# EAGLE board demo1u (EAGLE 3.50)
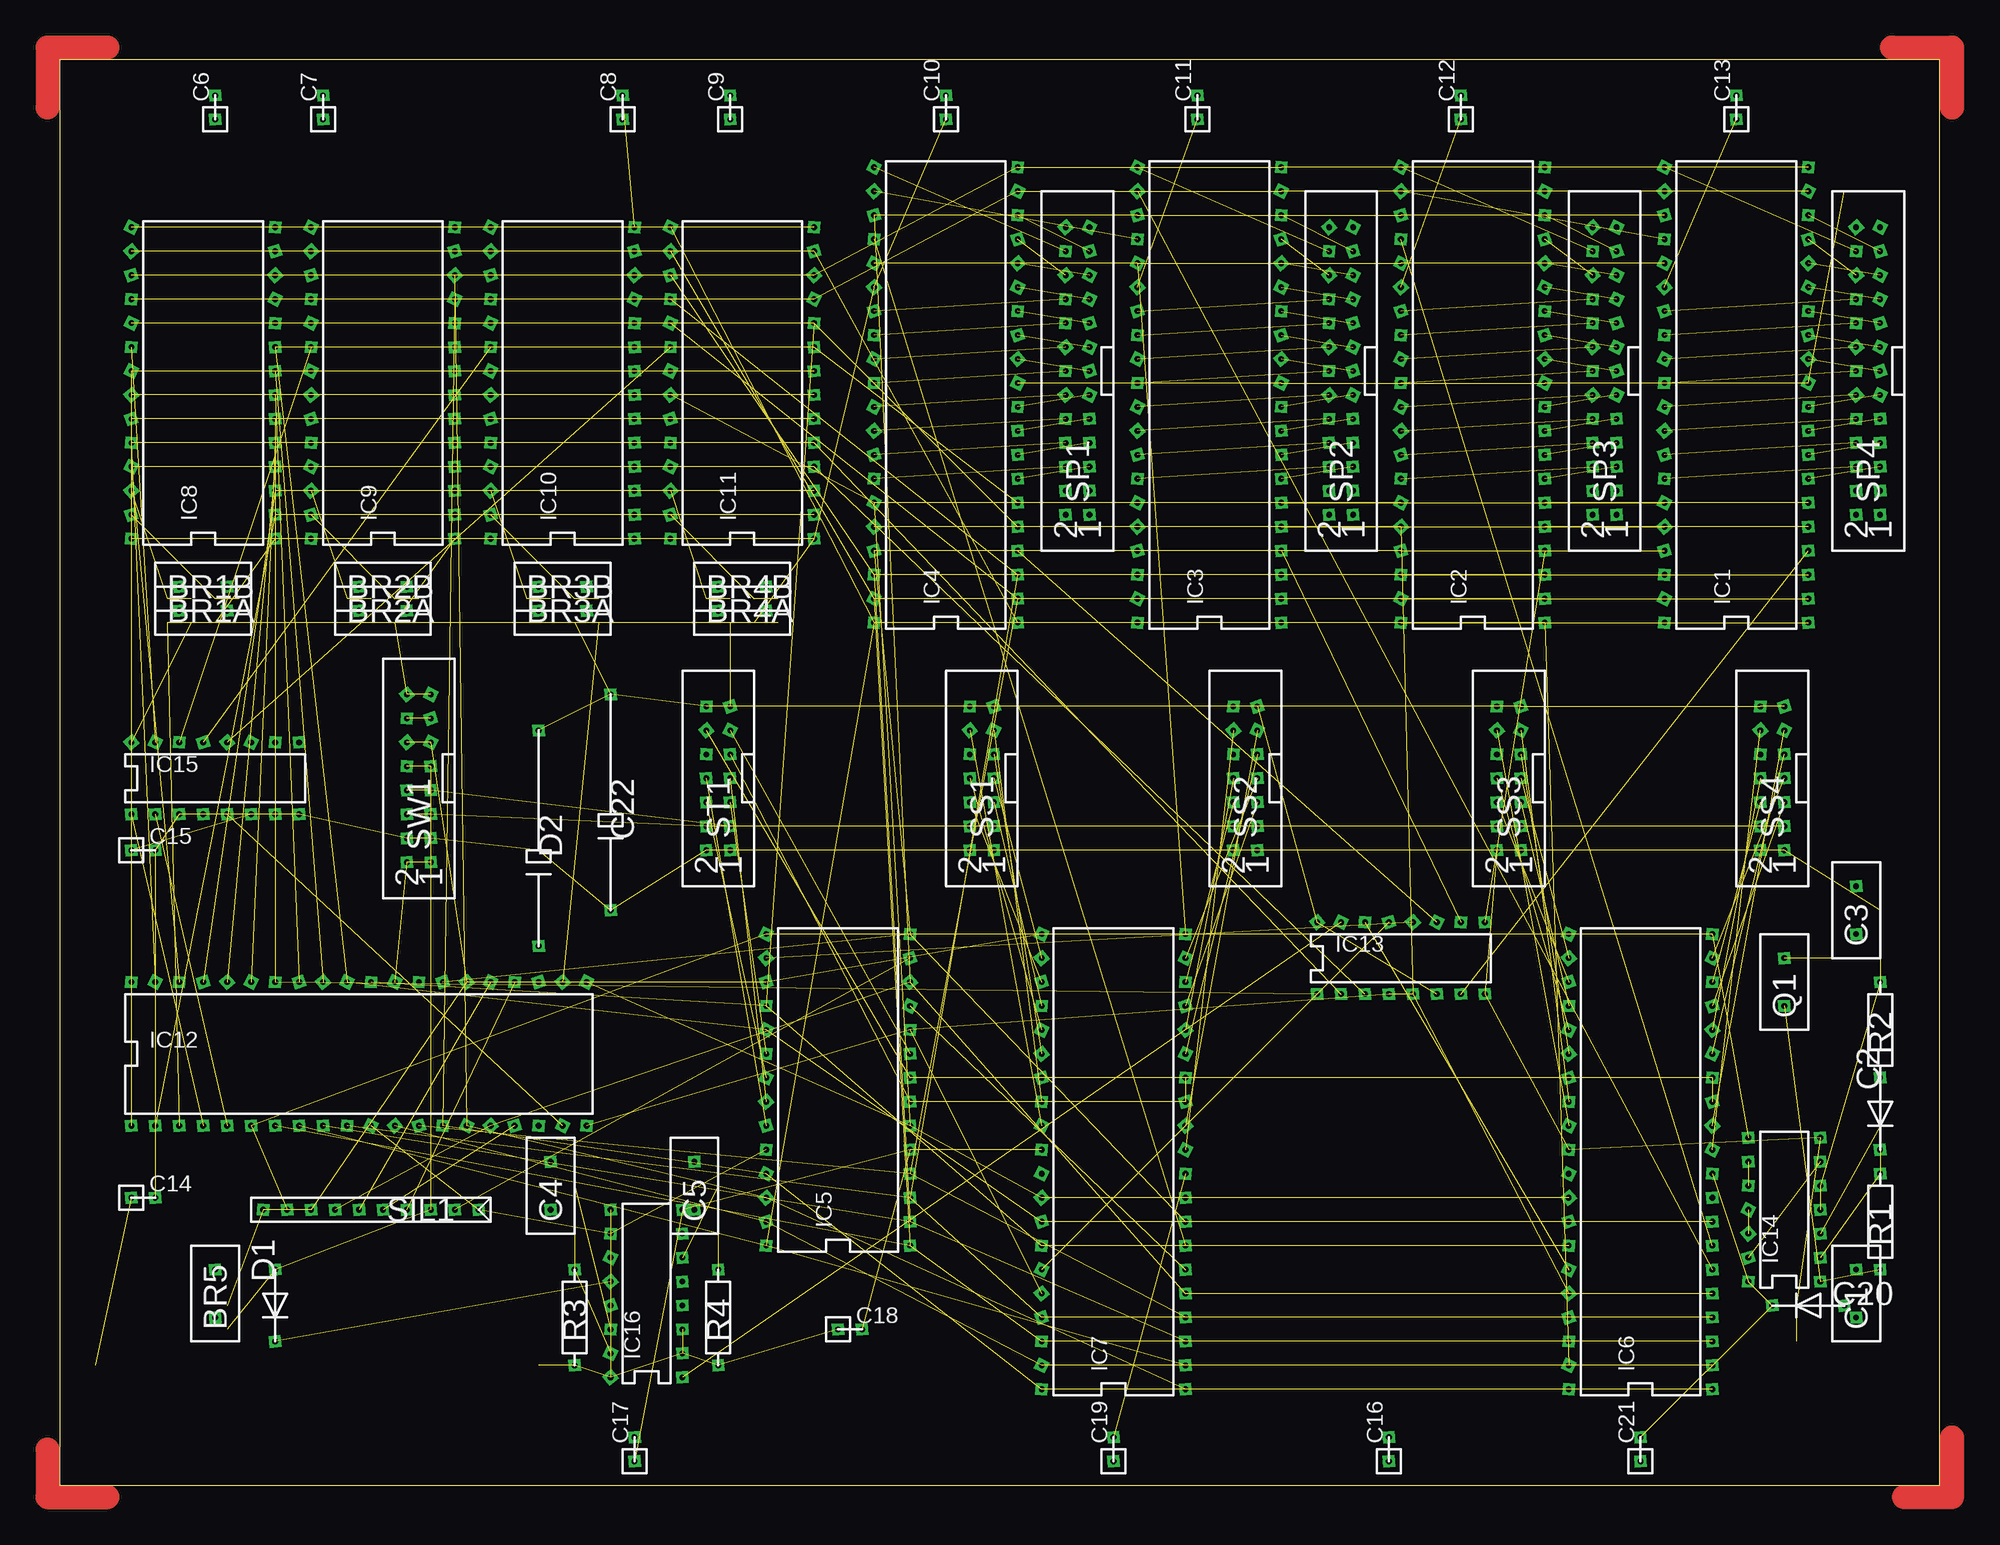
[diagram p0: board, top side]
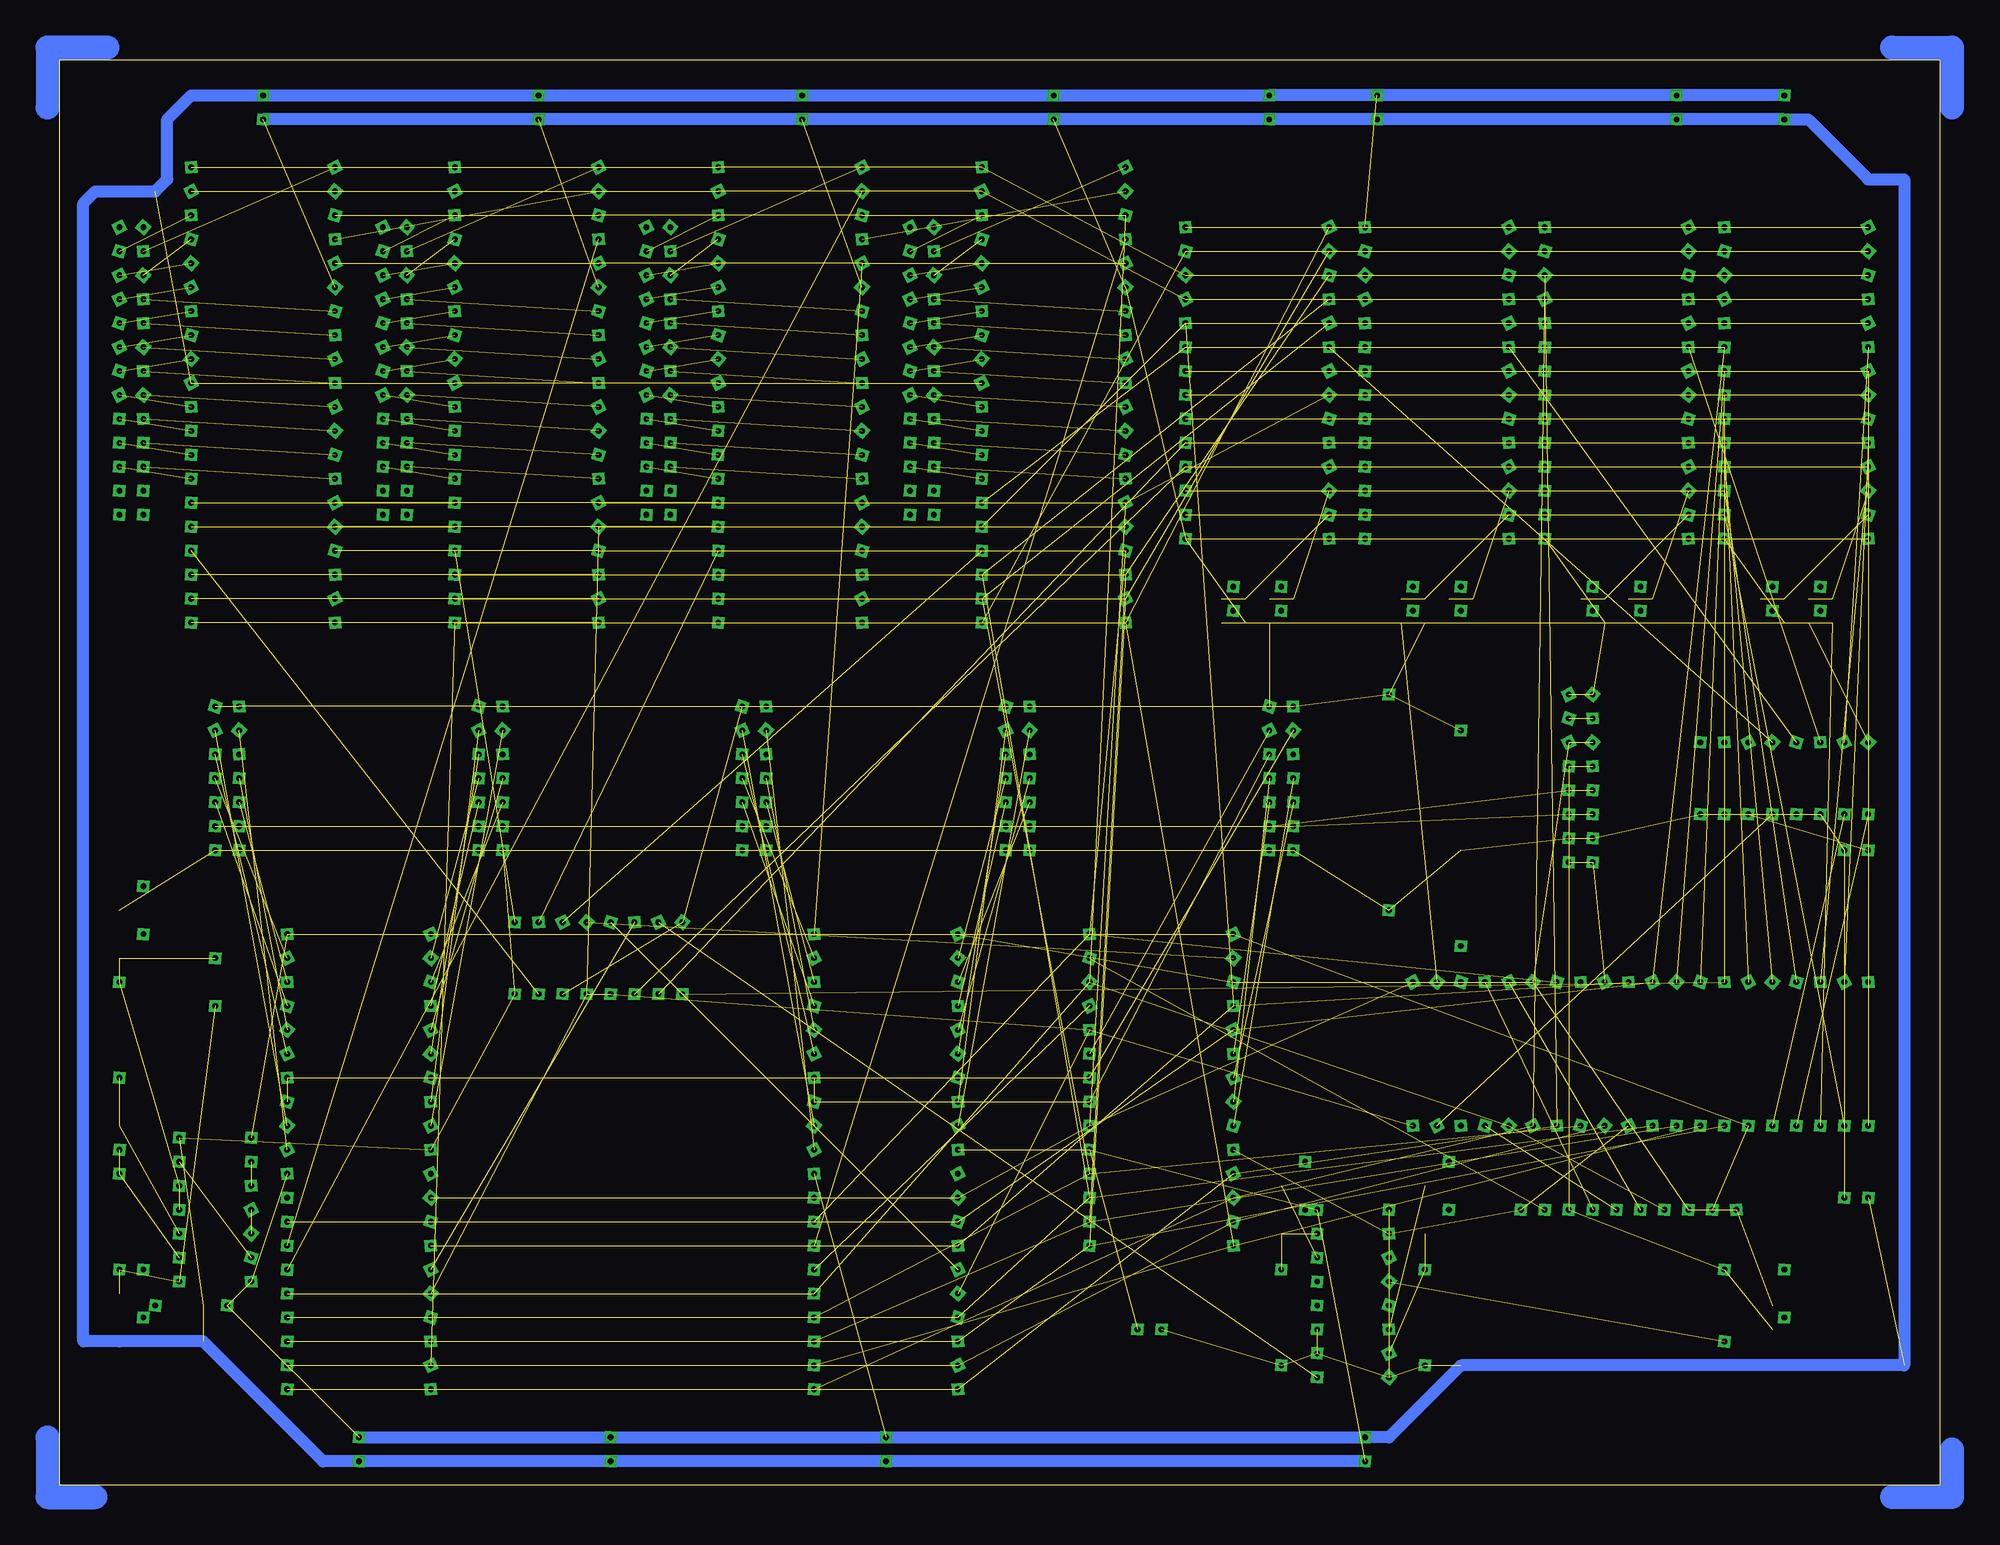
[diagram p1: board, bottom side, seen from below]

Size 199.36 x 151.16 mm. Coordinates in mm from the lower left corner, seen from the top.
Outline: 0,0.03 199.37,0 199.37,151.16 0,151.16 0,0.03
Copper layers used: Top, Bottom
tRestrict: area 5.1,5.1 to 7.6,7.6; area 2.5,2.6 to 10.2,10.2; area 5.1,142.3 to 7.6,144.8; area 2.5,139.7 to 10.2,147.3; area 191.8,5.1 to 194.3,7.6; area 189.2,2.6 to 196.9,10.2; area 191.8,142.3 to 194.3,144.8; area 189.2,139.7 to 196.9,147.3; area 34.3,6.4 to 36.8,8.9; area 47,6.4 to 49.5,8.9; area 34.3,141 to 36.8,143.5; area 47,141 to 49.5,143.5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
bRestrict: area 5.1,5.1 to 7.6,7.6; area 2.5,2.6 to 10.2,10.2; area 5.1,142.3 to 7.6,144.8; area 2.5,139.7 to 10.2,147.3; area 191.8,5.1 to 194.3,7.6; area 189.2,2.6 to 196.9,10.2; area 191.8,142.3 to 194.3,144.8; area 189.2,139.7 to 196.9,147.3; area 34.3,6.4 to 36.8,8.9; area 47,6.4 to 49.5,8.9; area 34.3,141 to 36.8,143.5; area 47,141 to 49.5,143.5

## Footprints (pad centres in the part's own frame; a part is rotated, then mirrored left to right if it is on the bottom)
 = drill 0.61 pad 1.27 square:  2.54,2.54;  7.62,2.54
.5 = drill 0.61 pad 1.27 square:  0,0;  7.62,0
.5' = drill 0.61 pad 1.27 square:  0,0;  2.54,0
2.5 = drill 0.61 pad 1.27 square:  0,0;  22.86,0
L40 = drill 0.61 pad 1.27 square:  0,0;  2.54,0;  5.08,0;  7.62,0;  10.16,0;  12.7,0;  15.24,0;  17.78,0;  20.32,0;  22.86,0;  25.4,0;  27.94,0;  30.48,0;  33.02,0;  35.56,0;  38.1,0;  40.64,0;  43.18,0;  45.72,0;  48.26,0;  48.26,15.24;  45.72,15.24;  43.18,15.24;  40.64,15.24;  38.1,15.24;  35.56,15.24;  33.02,15.24;  30.48,15.24;  27.94,15.24;  25.4,15.24;  22.86,15.24;  20.32,15.24;  17.78,15.24;  15.24,15.24;  12.7,15.24;  10.16,15.24;  7.62,15.24;  5.08,15.24;  2.54,15.24;  0,15.24
L28 = drill 0.61 pad 1.27 square:  0,0;  2.54,0;  5.08,0;  7.62,0;  10.16,0;  12.7,0;  15.24,0;  17.78,0;  20.32,0;  22.86,0;  25.4,0;  27.94,0;  30.48,0;  33.02,0;  33.02,15.24;  30.48,15.24;  27.94,15.24;  25.4,15.24;  22.86,15.24;  20.32,15.24;  17.78,15.24;  15.24,15.24;  12.7,15.24;  10.16,15.24;  7.62,15.24;  5.08,15.24;  2.54,15.24;  0,15.24
L16 = drill 0.61 pad 1.27 square:  0,0;  2.54,0;  5.08,0;  7.62,0;  10.16,0;  12.7,0;  15.24,0;  17.78,0;  17.78,7.62;  15.24,7.62;  12.7,7.62;  10.16,7.62;  7.62,7.62;  5.08,7.62;  2.54,7.62;  0,7.62
L14 = drill 0.61 pad 1.27 square:  0,0;  2.54,0;  5.08,0;  7.62,0;  10.16,0;  12.7,0;  15.24,0;  15.24,7.62;  12.7,7.62;  10.16,7.62;  7.62,7.62;  5.08,7.62;  2.54,7.62;  0,7.62
0 = drill 0.61 pad 1.27 square:  0,0;  10.16,0
10 = drill 0.61 pad 1.27 square:  1.27,1.27;  3.81,1.27;  6.35,1.27;  8.89,1.27;  11.43,1.27;  13.97,1.27;  16.51,1.27;  19.05,1.27;  21.59,1.27;  24.13,1.27
26 = drill 0.61 pad 1.27 square:  3.81,2.54;  3.81,5.08;  6.35,2.54;  6.35,5.08;  8.89,2.54;  8.89,5.08;  11.43,2.54;  11.43,5.08;  13.97,2.54;  13.97,5.08;  16.51,2.54;  16.51,5.08;  19.05,2.54;  19.05,5.08;  21.59,2.54;  21.59,5.08;  24.13,2.54;  24.13,5.08;  26.67,2.54;  26.67,5.08;  29.21,2.54;  29.21,5.08;  31.75,2.54;  31.75,5.08;  34.29,2.54;  34.29,5.08
14 = drill 0.61 pad 1.27 square:  3.81,2.54;  3.81,5.08;  6.35,2.54;  6.35,5.08;  8.89,2.54;  8.89,5.08;  11.43,2.54;  11.43,5.08;  13.97,2.54;  13.97,5.08;  16.51,2.54;  16.51,5.08;  19.05,2.54;  19.05,5.08
16 = drill 0.61 pad 1.27 square:  3.81,2.54;  3.81,5.08;  6.35,2.54;  6.35,5.08;  8.89,2.54;  8.89,5.08;  11.43,2.54;  11.43,5.08;  13.97,2.54;  13.97,5.08;  16.51,2.54;  16.51,5.08;  19.05,2.54;  19.05,5.08;  21.59,2.54;  21.59,5.08

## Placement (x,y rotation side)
BR1A  []  10.16,90.2 0 top
BR1B  PAGE 1  []  10.16,92.74 0 top
BR2A  []  29.21,90.2 0 top
BR2B  PAGE 2  []  29.21,92.74 0 top
BR3A  []  48.26,90.2 0 top
BR3B  PAGE 3  []  48.26,92.74 0 top
BR4A  []  67.31,90.2 0 top
BR4B  PAGE 4  []  67.31,92.74 0 top
BR5  DOG  []  19.05,15.27 90 top
C1  22 PF  []  193.04,15.27 90 top
C2  10 NF  [.5]  193.04,35.59 90 top
C3  22 PF  []  193.04,55.91 90 top
C4  10 UF  []  54.61,26.7 90 top
C5  10 UF  []  69.85,26.7 90 top
C6  10 NF  [.5']  16.51,144.81 90 top
C7  10 NF  [.5']  27.94,144.81 90 top
C8  10 NF  [.5']  59.69,144.81 90 top
C9  10 NF  [.5']  71.12,144.81 90 top
C10  10 NF  [.5']  93.98,144.81 90 top
C11  10 NF  [.5']  120.65,144.81 90 top
C12  10 NF  [.5']  148.59,144.81 90 top
C13  10 NF  [.5']  177.8,144.81 90 top
C14  10 NF  [.5']  7.62,30.51 0 top
C15  10 NF  [.5']  7.62,67.34 0 top
C16  10 NF  [.5']  140.97,2.57 90 top
C17  10 NF  [.5']  60.96,2.57 90 top
C18  10 NF  [.5']  82.55,16.54 0 top
C19  10 NF  [.5']  111.76,2.57 90 top
C20  10 NF  [.5]  181.61,19.08 0 top
C21  10 NF  [.5']  167.64,2.57 90 top
C22  100 UF  [2.5]  58.42,83.85 270 top
D1  1NXXX  [.5]  22.86,15.27 90 top
D2  1N4001  [2.5]  50.8,80.04 270 top
E$1  [AWING]  not placed on the board
IC1  PIO 4  [L40]  185.42,91.47 90 top
IC2  PIO 3  [L40]  157.48,91.47 90 top
IC3  PIO 2  [L40]  129.54,91.47 90 top
IC4  PIO 1  [L40]  101.6,91.47 90 top
IC5  CTC  [L28]  90.17,25.43 90 top
IC6  DART 2  [L40]  175.26,10.19 90 top
IC7  DART 1  [L40]  119.38,10.19 90 top
IC8  PAGE 0  [L28]  22.86,100.36 90 top
IC9  PAGE 1  [L28]  41.91,100.36 90 top
IC10  PAGE 2  [L28]  60.96,100.36 90 top
IC11  PAGE 3  [L28]  80.01,100.36 90 top
IC12  Z80CPU  [L40]  7.62,38.13 0 top
IC13  74LS138  [L16]  133.35,52.1 0 top
IC14  7404  [L14]  186.69,21.62 90 top
IC15  74LS138  [L16]  7.62,71.15 0 top
IC16  74LS123  [L16]  66.04,11.46 90 top
Q1  2 MHZ  []  185.42,48.29 90 top
R1  1,5 K  [0]  193.04,22.89 90 top
R2  3,3 K  [0]  193.04,43.21 90 top
R3  33 K  [0]  54.61,12.73 90 top
R4  33 K  [0]  69.85,12.73 90 top
SIL1  2,2 K  [10]  45.72,30.51 180 top
SP1  PAR 1  [26]  111.76,99.09 90 top
SP2  PAR 2  [26]  139.7,99.09 90 top
SP3  PAR 3  [26]  167.64,99.09 90 top
SP4  PAR 4  [26]  195.58,99.09 90 top
SS1  SER 1  [14]  101.6,63.53 90 top
SS2  SER 2  [14]  129.54,63.53 90 top
SS3  SER 3  [14]  157.48,63.53 90 top
SS4  SER 4  [14]  185.42,63.53 90 top
ST1  TIMER  [14]  73.66,63.53 90 top
SW1  POWER  [16]  41.91,62.26 90 top

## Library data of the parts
BR1A BR1B BR2A BR2B BR3A BR3B BR4A BR4B BR5 C1-C5 C20 C22 D1 D2 Q1 R1-R4 SIL1 SP1-SP4 SS1-SS4 ST1 SW1 = ARIADNE
C6-C19 C21 E$1 IC1-IC16 = EAGLE

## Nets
+5,2V: BR1A. BR2A. BR3A. BR4A. C6. C7. C8. C9. C10. C11. C12. C13. C14. C15. C16. C17. C18. C19. C20. C21. C22. D2. IC1. IC2. IC3. IC4. IC5. IC6. IC7. IC8. IC9. IC10. IC11. IC12. IC13. IC14. IC15. IC16. R3. R4. SIL1. SS1. SS2. SS3. SS4. ST1. SW1.
+12V: SS1. SS2. SS3. SS4. ST1. SW1.
-12V: SS1. SS2. SS3. SS4. ST1. SW1.
A0: IC1. IC2. IC3. IC4. IC5. IC6. IC7. IC8. IC9. IC10. IC11. IC12.
A1: IC1. IC2. IC3. IC4. IC5. IC6. IC7. IC8. IC9. IC10. IC11. IC12.
A2: IC8. IC9. IC10. IC11. IC12.
A3: IC8. IC9. IC10. IC11. IC12.
A4: IC8. IC9. IC10. IC11. IC12. IC13.
A5: IC8. IC9. IC10. IC11. IC12. IC13.
A6: IC8. IC9. IC10. IC11. IC12. IC13.
A7: IC8. IC9. IC10. IC11. IC12.
A8: IC8. IC9. IC10. IC11. IC12.
A9: IC8. IC9. IC10. IC11. IC12.
A10: IC8. IC9. IC10. IC11. IC12.
A11: IC8. IC9. IC10. IC11. IC12.
A12: IC8. IC9. IC10. IC11. IC12.
A13: BR1A. BR2A. BR3A. BR4A. IC12.
A13_1: BR1B. IC8.
A13_2: BR2B. IC9.
A13_3: BR3B. IC10.
A13_4: BR4B. IC11.
A14: IC12. IC15.
A15: IC12. IC15.
ARDY1: IC4. SP1.
ARDY2: IC3. SP2.
ARDY3: IC2. SP3.
ARDY4: IC1. SP4.
ASTB2: IC3. SP2.
ASTB3: IC2. SP3.
ASTB4: IC1. SP4.
ATSB1: IC4. SP1.
BRDY1: IC4. SP1.
BRDY2: IC3. SP2.
BRDY3: IC2. SP3.
BRDY4: IC1. SP4.
BSTB1: IC4. SP1.
BSTB2: IC3. SP2.
BSTB3: IC2. SP3.
BSTB4: IC1. SP4.
BUSRQ: IC12. SIL1.
CI1: C3. IC14. Q1. R2.
CI2: IC14.
CI3: IC14.
CI4: IC14.
CI5: C1. IC14. Q1. R1.
CI6: C2. IC14. R1.
CI7: C2. IC14. R2.
CK: IC1. IC2. IC3. IC4. IC5. IC6. IC7. IC12. IC14. SIL1.
CLK/TRG0: IC5. ST1.
CLK/TRG1: IC5. ST1.
CLK/TRG2: IC5. ST1.
CLK/TRG3: IC5. ST1.
CTSA1: IC7. SS2.
CTSA2: IC6. SS4.
CTSB1: IC7. SS1.
CTSB2: IC6. SS3.
D0: IC1. IC2. IC3. IC4. IC5. IC6. IC7. IC8. IC9. IC10. IC11. IC12.
D1: IC1. IC2. IC3. IC4. IC5. IC6. IC7. IC8. IC9. IC10. IC11. IC12.
D2: IC1. IC2. IC3. IC4. IC5. IC6. IC7. IC8. IC9. IC10. IC11. IC12.
D3: IC1. IC2. IC3. IC4. IC5. IC6. IC7. IC8. IC9. IC10. IC11. IC12.
D4: IC1. IC2. IC3. IC4. IC5. IC6. IC7. IC8. IC9. IC10. IC11. IC12.
D5: IC1. IC2. IC3. IC4. IC5. IC6. IC7. IC8. IC9. IC10. IC11. IC12.
D6: IC1. IC2. IC3. IC4. IC5. IC6. IC7. IC8. IC9. IC10. IC11. IC12.
D7: IC1. IC2. IC3. IC4. IC5. IC6. IC7. IC8. IC9. IC10. IC11. IC12.
DCDA1: IC7. SS2.
DCDA2: IC6. SS4.
DCDB1: IC7. SS1.
DCDB2: IC6. SS3.
DOG: BR5. D1. SIL1. SW1.
DTRA1: IC7. SS2.
DTRA2: IC6. SS4.
DTRB1: IC7. SS1.
DTRB2: IC6. SS3.
GND: C1. C3. C6. C7. C8. C9. C10. C11. C12. C13. C14. C15. C16. C17. C18. C19. C20. C21. C22. D2. IC1. IC2. IC3. IC4. IC5. IC6. IC7. IC8. IC9. IC10. IC11. IC12. IC13. IC14. IC15. IC16. SS1. SS2. SS3. SS4. ST1. SW1.
IEI1: IC5. SIL1.
IEI2: IC5. IC7.
IEI3: IC4. IC7.
IEI4: IC3. IC4.
IEI5: IC3. IC6.
IEI6: IC2. IC6.
IEI7: IC1. IC2.
INT: IC1. IC2. IC3. IC4. IC5. IC6. IC7. IC12. SIL1.
IORQ: IC1. IC2. IC3. IC4. IC5. IC6. IC7. IC12. IC13.
IOSEL0: IC13. IC16.
IOSEL1: IC6. IC13.
IOSEL2: IC7. IC13.
IOSEL3: IC5. IC13.
IOSEL4: IC4. IC13.
IOSEL5: IC3. IC13.
IOSEL6: IC2. IC13.
IOSEL7: IC1. IC13.
KEY: SW1.
M1: IC1. IC2. IC3. IC4. IC5. IC6. IC7. IC12.
MEMSEL0: IC8. IC15.
MEMSEL1: IC9. IC15.
MEMSEL2: IC10. IC15.
MEMSEL3: IC11. IC15.
MREQ: IC12. IC15.
NMI: IC12. SIL1.
PA01: IC4. SP1.
PA02: IC3. SP2.
PA03: IC2. SP3.
PA04: IC1. SP4.
PA11: IC4. SP1.
PA12: IC3. SP2.
PA13: IC2. SP3.
PA14: IC1. SP4.
PA21: IC4. SP1.
PA22: IC3. SP2.
PA23: IC2. SP3.
PA24: IC1. SP4.
PA31: IC4. SP1.
PA32: IC3. SP2.
PA33: IC2. SP3.
PA34: IC1. SP4.
PA41: IC4. SP1.
PA42: IC3. SP2.
PA43: IC2. SP3.
PA44: IC1. SP4.
PA51: IC4. SP1.
PA52: IC3. SP2.
PA53: IC2. SP3.
PA54: IC1. SP4.
PA61: IC4. SP1.
PA62: IC3. SP2.
PA63: IC2. SP3.
PA64: IC1. SP4.
PA71: IC4. SP1.
PA72: IC3. SP2.
PA73: IC2. SP3.
PA74: IC1. SP4.
PB01: IC4. SP1.
PB02: IC3. SP2.
PB03: IC2. SP3.
PB04: IC1. SP4.
PB11: IC4. SP1.
PB12: IC3. SP2.
PB13: IC2. SP3.
PB14: IC1. SP4.
PB21: IC4. SP1.
PB22: IC3. SP2.
PB23: IC2. SP3.
PB24: IC1. SP4.
PB31: IC4. SP1.
PB32: IC3. SP2.
PB33: IC2. SP3.
PB34: IC1. SP4.
PB41: IC4. SP1.
PB42: IC3. SP2.
PB43: IC2. SP3.
PB44: IC1. SP4.
PB51: IC4. SP1.
PB52: IC3. SP2.
PB53: IC2. SP3.
PB54: IC1. SP4.
PB61: IC4. SP1.
PB62: IC3. SP2.
PB63: IC2. SP3.
PB64: IC1. SP4.
PB71: IC4. SP1.
PB72: IC3. SP2.
PB73: IC2. SP3.
PB74: IC1. SP4.
RD: IC1. IC2. IC3. IC4. IC5. IC6. IC7. IC8. IC9. IC10. IC11. IC12.
RESET: BR5. IC5. IC6. IC7. IC12. SIL1. SW1.
RIA1: IC7. SS2.
RIA2: IC6. SS4.
RIB1: IC7. SS1.
RIB2: IC6. SS3.
RTSA1: IC7. SS2.
RTSA2: IC6. SS4.
RTSB1: IC7. SS1.
RTSB2: IC6. SS3.
RXDA1: IC7. SS2.
RXDA2: IC6. SS4.
RXDB1: IC7. SS1.
RXDB2: IC6. SS3.
TXDA1: IC7. SS2.
TXDA2: IC6. SS4.
TXDB1: IC7. SS1.
TXDB2: IC6. SS3.
WAIT: IC12. SIL1.
WI2: IC16.
WI3: D1. IC16.
WI5: C4. IC16.
WI6: C4. IC16. R3.
WI7: C5. IC16. R4.
WI8: C5. IC16.
WR: BR1A. BR2A. BR3A. BR4A. IC12.
WR_1: BR1B. IC8.
WR_2: BR2B. IC9.
WR_3: BR3B. IC10.
WR_4: BR4B. IC11.
ZC/TO0: IC5. IC6. IC7. ST1.
ZC/TO1: IC5. IC6. IC7. ST1.
ZC/TO2: IC5. ST1.

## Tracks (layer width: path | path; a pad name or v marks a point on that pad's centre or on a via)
+5,2V  (55 unrouted)
  Bottom 1.27: 177.8,144.81 148.59,144.81 120.65,144.81 93.98,144.81 71.12,144.81 59.69,144.81 27.94,144.81 16.51,144.81 13.97,144.81 7.62,138.46 3.81,138.46 3.81,12.73 50.8,12.73 58.42,5.11 C17. C19. C16. C21.
+12V  (6 unrouted)
-12V  (6 unrouted)
A0  (11 unrouted)
A1  (11 unrouted)
A2  (4 unrouted)
A3  (4 unrouted)
A4  (5 unrouted)
A5  (5 unrouted)
A6  (5 unrouted)
A7  (4 unrouted)
A8  (4 unrouted)
A9  (4 unrouted)
A10  (4 unrouted)
A11  (4 unrouted)
A12  (4 unrouted)
A13  (4 unrouted)
A13_1  (2 unrouted)
A13_2  (2 unrouted)
A13_3  (2 unrouted)
A13_4  (2 unrouted)
A14  (1 unrouted)
A15  (1 unrouted)
ARDY1  (1 unrouted)
ARDY2  (1 unrouted)
ARDY3  (1 unrouted)
ARDY4  (1 unrouted)
ASTB2  (1 unrouted)
ASTB3  (1 unrouted)
ASTB4  (1 unrouted)
ATSB1  (1 unrouted)
BRDY1  (1 unrouted)
BRDY2  (1 unrouted)
BRDY3  (1 unrouted)
BRDY4  (1 unrouted)
BSTB1  (1 unrouted)
BSTB2  (1 unrouted)
BSTB3  (1 unrouted)
BSTB4  (1 unrouted)
BUSRQ  (1 unrouted)
CI1  (4 unrouted)
CI2  (1 unrouted)
CI3  (1 unrouted)
CI4  (1 unrouted)
CI5  (3 unrouted)
CI6  (2 unrouted)
CI7  (2 unrouted)
CK  (9 unrouted)
CLK/TRG0  (1 unrouted)
CLK/TRG1  (1 unrouted)
CLK/TRG2  (1 unrouted)
CLK/TRG3  (1 unrouted)
CTSA1  (1 unrouted)
CTSA2  (1 unrouted)
CTSB1  (1 unrouted)
CTSB2  (1 unrouted)
D0  (11 unrouted)
D1  (11 unrouted)
D2  (11 unrouted)
D3  (11 unrouted)
D4  (11 unrouted)
D5  (11 unrouted)
D6  (11 unrouted)
D7  (11 unrouted)
DCDA1  (1 unrouted)
DCDA2  (1 unrouted)
DCDB1  (1 unrouted)
DCDB2  (1 unrouted)
DOG  (4 unrouted)
DTRA1  (1 unrouted)
DTRA2  (1 unrouted)
DTRB1  (1 unrouted)
DTRB2  (1 unrouted)
GND  (38 unrouted)
  Bottom 1.27: C6. C7. C8. C9. C10. C11. C12. C13. 185.42,147.35 187.96,144.81 187.96,138.46 189.23,137.19 195.58,137.19 196.85,135.92 196.85,15.27 193.04,15.27 184.15,15.27 171.45,2.57 167.64,2.57 140.97,2.57 111.76,2.57 60.96,2.57
IEI1  (1 unrouted)
IEI2  (1 unrouted)
IEI3  (1 unrouted)
IEI4  (1 unrouted)
IEI5  (1 unrouted)
IEI6  (1 unrouted)
IEI7  (1 unrouted)
INT  (8 unrouted)
IORQ  (9 unrouted)
IOSEL0  (1 unrouted)
IOSEL1  (1 unrouted)
IOSEL2  (1 unrouted)
IOSEL3  (1 unrouted)
IOSEL4  (1 unrouted)
IOSEL5  (1 unrouted)
IOSEL6  (1 unrouted)
IOSEL7  (1 unrouted)
KEY  (1 unrouted)
M1  (7 unrouted)
MEMSEL0  (1 unrouted)
MEMSEL1  (1 unrouted)
MEMSEL2  (1 unrouted)
MEMSEL3  (1 unrouted)
MREQ  (2 unrouted)
NMI  (1 unrouted)
PA01  (1 unrouted)
PA02  (1 unrouted)
PA03  (1 unrouted)
PA04  (1 unrouted)
PA11  (1 unrouted)
PA12  (1 unrouted)
PA13  (1 unrouted)
PA14  (1 unrouted)
PA21  (1 unrouted)
PA22  (1 unrouted)
PA23  (1 unrouted)
PA24  (1 unrouted)
PA31  (1 unrouted)
PA32  (1 unrouted)
PA33  (1 unrouted)
PA34  (1 unrouted)
PA41  (1 unrouted)
PA42  (1 unrouted)
PA43  (1 unrouted)
PA44  (1 unrouted)
PA51  (1 unrouted)
PA52  (1 unrouted)
PA53  (1 unrouted)
PA54  (1 unrouted)
PA61  (1 unrouted)
PA62  (1 unrouted)
PA63  (1 unrouted)
PA64  (1 unrouted)
PA71  (1 unrouted)
PA72  (1 unrouted)
PA73  (1 unrouted)
PA74  (1 unrouted)
PB01  (1 unrouted)
PB02  (1 unrouted)
PB03  (1 unrouted)
PB04  (1 unrouted)
PB11  (1 unrouted)
PB12  (1 unrouted)
PB13  (1 unrouted)
PB14  (1 unrouted)
PB21  (1 unrouted)
PB22  (1 unrouted)
PB23  (1 unrouted)
PB24  (1 unrouted)
PB31  (1 unrouted)
PB32  (1 unrouted)
PB33  (1 unrouted)
PB34  (1 unrouted)
PB41  (1 unrouted)
PB42  (1 unrouted)
PB43  (1 unrouted)
PB44  (1 unrouted)
PB51  (1 unrouted)
PB52  (1 unrouted)
PB53  (1 unrouted)
PB54  (1 unrouted)
PB61  (1 unrouted)
PB62  (1 unrouted)
PB63  (1 unrouted)
PB64  (1 unrouted)
PB71  (1 unrouted)
PB72  (1 unrouted)
PB73  (1 unrouted)
PB74  (1 unrouted)
RD  (11 unrouted)
RESET  (8 unrouted)
RIA1  (1 unrouted)
RIA2  (1 unrouted)
RIB1  (1 unrouted)
RIB2  (1 unrouted)
RTSA1  (1 unrouted)
RTSA2  (1 unrouted)
RTSB1  (1 unrouted)
RTSB2  (1 unrouted)
RXDA1  (1 unrouted)
RXDA2  (1 unrouted)
RXDB1  (1 unrouted)
RXDB2  (1 unrouted)
S$1
  Bottom 2.54: -1.27,3.84 -1.27,-1.24 5.08,-1.24
S$2
  Top 2.54: -1.27,3.84 -1.27,-1.24 5.08,-1.24
S$3
  Top 2.54: 5.08,152.43 -1.27,152.43 -1.27,146.08
S$4
  Bottom 2.54: 5.08,152.43 -1.27,152.43 -1.27,146.08
S$5
  Bottom 2.54: 194.31,152.43 200.66,152.43 200.66,146.08
S$6
  Top 2.54: 194.31,152.43 200.66,152.43 200.66,146.08
S$7
  Top 2.54: 200.66,5.11 200.66,-1.24 195.58,-1.24
S$8
  Bottom 2.54: 200.66,5.11 200.66,-1.24 195.58,-1.24
TXDA1  (1 unrouted)
TXDA2  (1 unrouted)
TXDB1  (1 unrouted)
TXDB2  (1 unrouted)
WAIT  (1 unrouted)
WI2  (1 unrouted)
WI3  (1 unrouted)
WI5  (1 unrouted)
WI6  (2 unrouted)
WI7  (2 unrouted)
WI8  (1 unrouted)
WR  (4 unrouted)
WR_1  (2 unrouted)
WR_2  (2 unrouted)
WR_3  (2 unrouted)
WR_4  (2 unrouted)
ZC/TO0  (5 unrouted)
ZC/TO1  (3 unrouted)
ZC/TO2  (1 unrouted)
